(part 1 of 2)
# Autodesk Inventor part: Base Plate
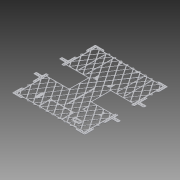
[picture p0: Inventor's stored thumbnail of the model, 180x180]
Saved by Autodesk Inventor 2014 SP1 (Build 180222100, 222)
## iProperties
Created: 2014-06
Part Number: Base Plate
Material: Aluminum 6061
Document SubType Name: Sheet Metal
Designer: Michael
Density: 2.71 g/cm^3
Sheet Metal Rule: Default
Appearance: Aluminum - Flat
Mass: 1196.55 g
Surface Area: 3779.14 cm^2
Volume: 441.53 cm^3
Author: Michael
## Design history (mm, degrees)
node "Face1"
  sketch "Sketch1"
    geometry: L1 (-304.8, -349.25)-(304.8, -349.25); L2 (304.8, -349.25)-(304.8, 349.25); L3 (304.8, 349.25)-(-304.8, 349.25); L4 (-304.8, 349.25)-(-304.8, -349.25); L5 (-304.8, -349.25)-(304.8, 349.25); L6 (304.8, -349.25)-(-304.8, 349.25); 1 further point
    constraints: 12 end point, 2 midpoint, 2 parallel, 1 horizontal, 1 perpendicular
    dimensions: "d0" = 698.5 distance between parallel lines of L1 L3; "d1" = 609.6 distance between parallel lines of L2 L4
sketch "Sketch2"
  geometry: L1 (-304.8, 349.25)-(304.8, 349.25) reference; L2 (-304.8, -349.25)-(-304.8, 349.25) reference; C1 r 2.489 at (-292.1, 336.55); 1 further point
  constraints: 1 centre point
  dimensions: "d3" = 4.9784 diameter of C1; "d4" = 12.7 distance from line of L1 C1.centre; "d5" = 12.7 distance from line of L2 C1.centre
cut "Cut1" sketch "Sketch2" dims "d6" = 3.175 (= Thickness), "d7" = 0
mirror "Mirror1"
sketch "Sketch3"
  geometry: L1 (-304.8, 349.25)-(304.8, 349.25) reference; C1 r 2.489 at (-12.7, 336.55) reference; C2 r 2.489 at (0, 336.55); 2 further points
  constraints: 1 centre point, 1 horizontal alignment, 1 midpoint, 1 vertical alignment
  dimensions: "d11" = 4.9784 diameter of C2
cut "Cut2" sketch "Sketch3" dims "d12" = 3.175 (= Thickness), "d13" = 0
mirror "Mirror2"
mirror "Mirror3"
sketch "Sketch4"
  geometry: L1 (-304.8, -349.25)-(-304.8, 349.25) reference; C1 r 2.489 at (-292.1, 6.35) reference; C2 r 2.489 at (-292.1, 0); 2 further points
  constraints: 1 centre point, 1 horizontal alignment, 1 midpoint, 1 vertical alignment
  dimensions: "d17" = 4.9784 diameter of C2
cut "Cut3" sketch "Sketch4" dims "d18" = 3.175 (= Thickness), "d19" = 0
mirror "Mirror4"
feature "Corner Round1" dims "d20" = 6.35
sketch "Sketch5" dims "d35" = 25.4, "d37" = 12.7 (= d29)
  geometry: L1 (-304.8, -342.9)-(-304.8, 342.9) reference; L2 (298.45, -349.25)-(-298.45, -349.25) reference; L3 (304.8, 342.9)-(304.8, -342.9) reference; L4 (-298.45, 349.25)-(298.45, 349.25) reference; L5 (-222.25, 346.075)-(-222.25, 336.55); L6 (-219.075, 333.375)-(-200.025, 333.375); L7 (-225.425, 349.25)-(-298.45, 349.25); L8 (-196.85, 349.25)-(298.45, 349.25); L9 (-184.15, 333.375)-(-180.975, 333.375); L10 (-180.975, 333.375)-(-161.925, 333.375); L11 (-142.875, 333.375)-(-123.825, 333.375); L12 (-104.775, 333.375)-(-85.725, 333.375); L13 (-66.675, 333.375)-(-47.625, 333.375); L14 (-28.575, 333.375)-(-9.525, 333.375); L15 (0, 336.55)-(0, 349.25); L16 (-196.85, 349.25)-(-225.425, 349.25); L17 (-225.425, 349.25)-(0, 349.25); L18 (-222.25, 346.075)-(-222.25, 336.55); L19 (-219.075, 333.375)-(-200.025, 333.375); C1 r 2.489 at (292.1, 0) reference; C2 r 2.489 at (-292.1, 0) reference; C3 r 2.489 at (292.1, -6.35) reference; C4 r 2.489 at (292.1, -19.05) reference; C5 r 2.489 at (292.1, -31.75) reference; C6 r 2.489 at (292.1, -44.45) reference; C7 r 2.489 at (292.1, -57.15) reference; C8 r 2.489 at (292.1, -69.85) reference; C9 r 2.489 at (292.1, -82.55) reference; C10 r 2.489 at (292.1, -95.25) reference; C11 r 2.489 at (292.1, -107.95) reference; C12 r 2.489 at (292.1, -120.65) reference; C13 r 2.489 at (292.1, -133.35) reference; C14 r 2.489 at (292.1, -146.05) reference; C15 r 2.489 at (292.1, -158.75) reference; C16 r 2.489 at (292.1, -171.45) reference; C17 r 2.489 at (292.1, -184.15) reference; C18 r 2.489 at (292.1, -196.85) reference; C19 r 2.489 at (292.1, -209.55) reference; C20 r 2.489 at (292.1, -222.25) reference; C21 r 2.489 at (292.1, -234.95) reference; C22 r 2.489 at (292.1, -247.65) reference; C23 r 2.489 at (292.1, -260.35) reference; C24 r 2.489 at (292.1, -273.05) reference; C25 r 2.489 at (292.1, -285.75) reference; C26 r 2.489 at (292.1, -298.45) reference; C27 r 2.489 at (292.1, -311.15) reference; C28 r 2.489 at (292.1, -323.85) reference; C29 r 2.489 at (-292.1, -6.35) reference; C30 r 2.489 at (-292.1, -19.05) reference; C31 r 2.489 at (-292.1, -31.75) reference; C32 r 2.489 at (-292.1, -44.45) reference; C33 r 2.489 at (-292.1, -57.15) reference; C34 r 2.489 at (-292.1, -69.85) reference; C35 r 2.489 at (-292.1, -82.55) reference; C36 r 2.489 at (-292.1, -95.25) reference; C37 r 2.489 at (-292.1, -107.95) reference; C38 r 2.489 at (-292.1, -120.65) reference; C39 r 2.489 at (-292.1, -133.35) reference; C40 r 2.489 at (-292.1, -146.05) reference; C41 r 2.489 at (-292.1, -158.75) reference; C42 r 2.489 at (-292.1, -171.45) reference; C43 r 2.489 at (-292.1, -184.15) reference; C44 r 2.489 at (-292.1, -196.85) reference; C45 r 2.489 at (-292.1, -209.55) reference; C46 r 2.489 at (-292.1, -222.25) reference; C47 r 2.489 at (-292.1, -234.95) reference; C48 r 2.489 at (-292.1, -247.65) reference; C49 r 2.489 at (-292.1, -260.35) reference; C50 r 2.489 at (-292.1, -273.05) reference; C51 r 2.489 at (-292.1, -285.75) reference; C52 r 2.489 at (-292.1, -298.45) reference; C53 r 2.489 at (-292.1, -311.15) reference; C54 r 2.489 at (-292.1, -323.85) reference; C55 r 2.489 at (0, -336.55) reference; C56 r 2.489 at (12.7, -336.55) reference; C57 r 2.489 at (25.4, -336.55) reference; C58 r 2.489 at (38.1, -336.55) reference; C59 r 2.489 at (50.8, -336.55) reference; C60 r 2.489 at (63.5, -336.55) reference; C61 r 2.489 at (76.2, -336.55) reference; C62 r 2.489 at (88.9, -336.55) reference; C63 r 2.489 at (101.6, -336.55) reference; C64 r 2.489 at (114.3, -336.55) reference; A1 r 6.35 centre (-298.45, 342.9) between (-298.45, 349.25) and (-304.8, 342.9) reference; A2 r 6.35 centre (-298.45, -342.9) between (-304.8, -342.9) and (-298.45, -349.25) reference; A3 r 6.35 centre (298.45, -342.9) between (298.45, -349.25) and (304.8, -342.9) reference; A4 r 6.35 centre (298.45, 342.9) between (304.8, 342.9) and (298.45, 349.25) reference; A5 r 3.175 centre (-225.425, 346.075) between (-222.25, 346.075) and (-225.425, 349.25); A6 r 3.175 centre (-219.075, 336.55) between (-222.25, 336.55) and (-219.075, 333.375); A7 r 3.175 centre (-200.025, 336.55) between (-200.025, 333.375) and (-196.85, 336.55); A8 r 3.175 centre (-180.975, 336.55) between (-184.15, 336.55) and (-180.975, 333.375); A9 r 3.175 centre (-161.925, 336.55) between (-161.925, 333.375) and (-158.75, 336.55); A10 r 3.175 centre (-142.875, 336.55) between (-146.05, 336.55) and (-142.875, 333.375); A11 r 3.175 centre (-123.825, 336.55) between (-123.825, 333.375) and (-120.65, 336.55); A12 r 3.175 centre (-104.775, 336.55) between (-107.95, 336.55) and (-104.775, 333.375); A13 r 3.175 centre (-85.725, 336.55) between (-85.725, 333.375) and (-82.55, 336.55); A14 r 3.175 centre (-66.675, 336.55) between (-69.85, 336.55) and (-66.675, 333.375); A15 r 3.175 centre (-47.625, 336.55) between (-47.625, 333.375) and (-44.45, 336.55); A16 r 3.175 centre (-28.575, 336.55) between (-31.75, 336.55) and (-28.575, 333.375); A17 r 3.175 centre (-9.525, 336.55) between (-9.525, 333.375) and (-6.35, 336.55); A18 r 3.175 centre (-225.425, 346.075) between (-222.25, 346.075) and (-225.425, 349.25); A19 r 3.175 centre (-219.075, 336.55) between (-222.25, 336.55) and (-219.075, 333.375)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; 2 further points
  constraints: 30 end point, 30 point on circle, 23 tangent, 20 centre point, 6 collinear, 5 point on line, 4 perpendicular, 2 coincident, 2 equal radius, 2 horizontal alignment, 1 horizontal, 51 other
  dimensions: "d21" = 6.35 distance from line of C195.centre L5; "d23" = 15.875 distance between parallel lines of L4 L6; "d26" = 3.175 radius of A5; "d27" = 3.175 radius of A8; "d28" = 3.175 horizontal distance of A8.centre L9.start; "d29" = 12.7 diameter of C201; "d32" = 38.1 distance of L6.start L10.start; "d38" = 3.175 radius of A17
sketch "Sketch6" dims "d64" = 25.4
  geometry: L1 (298.45, -349.25)-(-298.45, -349.25) reference; L2 (-298.45, 349.25)-(298.45, 349.25) reference; L3 (277.812, -328.612)-(-277.813, -328.613); L4 (-277.813, -328.613)-(-277.812, 328.612); L5 (-277.812, 328.612)-(277.812, 328.613); L6 (277.812, 328.613)-(277.812, -328.612); L7 (277.812, -328.612)-(-277.812, 328.612); L8 (-277.813, -328.613)-(277.812, 328.613); L9 (271.463, -322.263)-(-271.463, -322.263); L10 (-271.463, -322.263)-(-271.463, 322.263); L11 (-271.463, 322.263)-(271.463, 322.263); L12 (271.463, 322.263)-(271.463, -322.263); L13 (271.463, -322.263)-(-271.463, 322.263); L14 (-271.463, -322.263)-(271.463, 322.263); L15 (-222.477, 306.978)-(-182.472, 266.972); L16 (-182.472, 266.972)-(-222.477, 226.967); L17 (-222.477, 226.967)-(-262.482, 266.972); L18 (-262.482, 266.972)-(-222.477, 306.978); L19 (-177.982, 262.482)-(-137.976, 222.477); L20 (-137.976, 222.477)-(-177.982, 182.472); L21 (-177.982, 182.472)-(-217.987, 222.477); L22 (-217.987, 222.477)-(-177.982, 262.482); L23 (-133.486, 226.967)-(-173.491, 266.972); L24 (-173.491, 266.972)-(-133.486, 306.978); L25 (-133.486, 306.978)-(-93.481, 266.972); L26 (-93.481, 266.972)-(-133.486, 226.967); L27 (-88.991, 262.482)-(-48.986, 222.477); L28 (-48.986, 222.477)-(-88.991, 182.472); L29 (-88.991, 182.472)-(-128.996, 222.477); L30 (-128.996, 222.477)-(-88.991, 262.482); L31 (-44.495, 306.978)-(-4.49, 266.972); L32 (-4.49, 266.972)-(-44.495, 226.967); L33 (-44.495, 226.967)-(-84.501, 266.972); L34 (-84.501, 266.972)-(-44.495, 306.978); L35 (0, 349.25)-(0, -349.25); L36 (0, 266.972)-(-4.49, 266.972); L37 (-262.482, 266.972)-(-271.462, 266.972); L38 (-182.472, 266.972)-(-173.491, 266.972); L39 (-4.49, 266.972)-(4.49, 266.972); L40 (-182.472, 177.982)-(-222.477, 137.976); L41 (-222.477, 137.976)-(-262.482, 177.982); L42 (-262.482, 177.982)-(-222.477, 217.987); L43 (-222.477, 217.987)-(-182.472, 177.982); L44 (-182.472, 88.991)-(-222.477, 48.986); L45 (-222.477, 48.986)-(-262.482, 88.991); L46 (-262.482, 88.991)-(-222.477, 128.996); L47 (-222.477, 128.996)-(-182.472, 88.991); L48 (-182.472, 0)-(-222.477, -40.005); L49 (-222.477, -40.005)-(-262.482, 0); L50 (-262.482, 0)-(-222.477, 40.005); L51 (-222.477, 40.005)-(-182.472, 0); L52 (-182.472, -88.991)-(-222.477, -128.996); L53 (-222.477, -128.996)-(-262.482, -88.991); L54 (-262.482, -88.991)-(-222.477, -48.986); L55 (-222.477, -48.986)-(-182.472, -88.991); L56 (-182.472, -177.982)-(-222.477, -217.987); L57 (-222.477, -217.987)-(-262.482, -177.982); L58 (-262.482, -177.982)-(-222.477, -137.976); L59 (-222.477, -137.976)-(-182.472, -177.982); L60 (-182.472, -266.972)-(-222.477, -306.978); L61 (-222.477, -306.978)-(-262.482, -266.972); L62 (-262.482, -266.972)-(-222.477, -226.967); L63 (-222.477, -226.967)-(-182.472, -266.972); L64 (-222.477, -306.978)-(-222.477, -322.263)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; 14 further points
  constraints: 126 end point, 10 midpoint, 7 equal length, 7 parallel, 4 collinear, 4 perpendicular, 4 point on line, 3 horizontal alignment, 2 horizontal, 1 vertical, 99 other
  dimensions: "d39" = 555.625 distance between parallel lines of L6 L4; "d40" = 657.225 distance between parallel lines of L5 L3; "d41" = 6.35 distance between parallel lines of L4 L10; "d42" = 6.35 distance between parallel lines of L5 L11; "d43" = 45 deg angle of L11 L18; "d44" = 6.35 distance between parallel lines of L16 L22; "d46" = 6.35 distance between parallel lines of L19 L23 (= d44); "d47" = 6.35 distance between parallel lines of L26 L30 (= d44); "d48" = 6.35 distance between parallel lines of L27 L33 (= d44); "d61" = 88.99079 distance of L15.end L40.start
cut "Cut4" sketch "Sketch6" dims "d50" = 3.175 (= Thickness), "d51" = 0
feature "Corner Round2" dims "d52" = 3.175
pattern_linear "Rectangular Pattern3" dims "d55" = 88.99079
pattern_linear "Rectangular Pattern4" dims "d58" = 88.99079
sketch "Sketch7"
  geometry: L1 (-260.237, 180.227)-(-224.722, 215.742) reference; L2 (-220.232, 304.733)-(-184.717, 269.217) reference; L3 (-224.722, 229.212)-(-260.237, 264.727) reference; L4 (-217.987, 222.477)-(-177.982, 262.482); L5 (-177.982, 262.482)-(-137.976, 222.477); L6 (-137.976, 222.477)-(-177.982, 182.472); L7 (-177.982, 182.472)-(-217.987, 222.477); 2 further points
  constraints: 8 end point, 3 collinear, 9 other
cut "Cut5" sketch "Sketch7" dims "d66" = 3.175 (derived), "d67" = 0
feature "Corner Round3" dims "d68" = 3.175
sketch "Sketch8"
  geometry: L1 (-260.237, 269.217)-(-224.722, 304.733) reference; L2 (-224.722, 229.212)-(-260.237, 264.727) reference; L3 (-298.45, 349.25)-(298.45, 349.25) reference; L4 (-262.482, 306.978)-(-262.482, 275.953); L5 (-262.482, 275.953)-(-231.457, 306.978); L6 (-231.457, 306.978)-(-262.482, 306.978); L7 (-224.722, 304.733)-(-222.477, 306.978); L8 (-220.232, 304.733)-(-222.477, 306.978); L9 (-260.237, 269.217)-(-262.482, 266.972); L10 (-260.237, 264.727)-(-262.482, 266.972); A1 r 3.175 centre (-222.477, 302.488) between (-220.232, 304.733) and (-224.722, 304.733) reference; A2 r 3.175 centre (-257.992, 266.972) between (-260.237, 269.217) and (-260.237, 264.727) reference; 1 further point
  constraints: 14 end point, 6 perpendicular, 4 tangent, 1 horizontal alignment, 1 parallel, 1 vertical alignment
  dimensions: "d75" = 6.35 distance between parallel lines of L1 L5
cut "Cut6" sketch "Sketch8" dims "d76" = 3.175 (derived), "d77" = 0
feature "Corner Round4" dims "d78" = 3.175
mirror "Mirror5"
mirror "Mirror6"
sketch "Sketch9"
  geometry: L1 (-171.246, 269.217)-(-135.731, 304.733) reference; L2 (-220.232, 304.733)-(-184.717, 269.217) reference; L3 (-298.45, 349.25)-(298.45, 349.25) reference; L4 (-213.497, 306.978)-(-177.982, 271.463); L5 (-177.982, 271.463)-(-142.466, 306.978); L6 (-142.466, 306.978)-(-213.497, 306.978); 2 further points
  constraints: 6 end point, 3 parallel, 1 horizontal alignment
  dimensions: "d79" = 6.35 distance between parallel lines of L2 L4; "d80" = 6.35 distance between parallel lines of L1 L5
cut "Cut7" sketch "Sketch9" dims "d81" = 3.175 (derived), "d82" = 0
feature "Corner Round5" dims "d83" = 3.175
pattern_linear "Rectangular Pattern6" dims "d86" = 88.99079
mirror "Mirror7"
sketch "Sketch11"
  geometry: L1 (-260.237, 180.227)-(-224.722, 215.742) reference; L2 (-224.722, 229.212)-(-260.237, 264.727) reference; L3 (-262.482, 257.992)-(-262.482, 186.962); L4 (-262.482, 186.962)-(-226.967, 222.477); L5 (-226.967, 222.477)-(-262.482, 257.992); 2 further points
  constraints: 6 end point, 2 parallel, 1 perpendicular, 1 vertical, 1 vertical alignment
  dimensions: "d91" = 6.35 distance between parallel lines of L2 L5; "d92" = 6.35 distance between parallel lines of L1 L4 (derived)
cut "Cut9" sketch "Sketch11" dims "d93" = 3.175 (derived), "d94" = 0
feature "Corner Round6" dims "d95" = 3.175
pattern_linear "Rectangular Pattern7" dims "d98" = 88.99079
mirror "Mirror8"
sketch "Sketch12" dims "d106" = 25.4, "d113" = 25.4
  geometry: L1 (-304.8, -342.9)-(-304.8, 342.9) reference; L2 (298.45, -349.25)-(-298.45, -349.25) reference; L3 (285.75, 330.2)-(-285.75, 330.2); L4 (-285.75, 330.2)-(-285.75, -330.2); L5 (-285.75, -330.2)-(285.75, -330.2); L6 (285.75, -330.2)-(285.75, 330.2); L7 (285.75, 330.2)-(-285.75, -330.2); L8 (-285.75, 330.2)-(285.75, -330.2); L9 (-255.746, -329.309)-(-280.325, -293.092); L10 (-280.325, -293.092)-(-255.746, -256.876); L11 (-255.746, -256.876)-(-231.167, -293.092); L12 (-231.167, -293.092)-(-255.746, -329.309); L13 (-280.325, -293.092)-(-285.75, -293.092); L14 (-255.746, -329.309)-(-255.746, -330.2); L15 (-223.493, -293.092)-(-198.914, -256.876); L16 (-198.914, -329.309)-(-223.493, -293.092); L17 (-198.914, -256.876)-(-174.335, -293.092); L18 (-174.335, -293.092)-(-198.914, -329.309); L19 (-166.66, -293.092)-(-142.081, -256.876); L20 (-142.081, -329.309)-(-166.66, -293.092); L21 (-142.081, -256.876)-(-117.502, -293.092); L22 (-117.502, -293.092)-(-142.081, -329.309); L23 (-109.828, -293.092)-(-85.249, -256.876); L24 (-85.249, -329.309)-(-109.828, -293.092); L25 (-85.249, -256.876)-(-60.67, -293.092); L26 (-60.67, -293.092)-(-85.249, -329.309); L27 (-52.995, -293.092)-(-28.416, -256.876); L28 (-28.416, -329.309)-(-52.995, -293.092); L29 (-28.416, -256.876)-(-3.837, -293.092); L30 (-3.837, -293.092)-(-28.416, -329.309); L31 (3.837, -293.092)-(28.416, -256.876); L32 (28.416, -329.309)-(3.837, -293.092); L33 (28.416, -256.876)-(52.995, -293.092); L34 (52.995, -293.092)-(28.416, -329.309); L35 (60.67, -293.092)-(85.249, -256.876); L36 (85.249, -329.309)-(60.67, -293.092); L37 (85.249, -256.876)-(109.828, -293.092); L38 (109.828, -293.092)-(85.249, -329.309); L39 (117.502, -293.092)-(142.081, -256.876); L40 (142.081, -329.309)-(117.502, -293.092); L41 (142.081, -256.876)-(166.66, -293.092); L42 (166.66, -293.092)-(142.081, -329.309); L43 (174.335, -293.092)-(198.914, -256.876); L44 (198.914, -329.309)-(174.335, -293.092); L45 (198.914, -256.876)-(223.493, -293.092); L46 (223.493, -293.092)-(198.914, -329.309); L47 (231.167, -293.092)-(255.746, -256.876); L48 (255.746, -329.309)-(231.167, -293.092); L49 (255.746, -256.876)-(280.325, -293.092); L50 (280.325, -293.092)-(255.746, -329.309); L51 (-255.746, -173.135)-(-231.167, -209.352); L52 (-255.746, -245.568)-(-280.325, -209.352); L53 (-231.167, -209.352)-(-255.746, -245.568); L54 (-280.325, -209.352)-(-255.746, -173.135); L55 (-198.914, -245.568)-(-223.493, -209.352); L56 (-174.335, -209.352)-(-198.914, -245.568); L57 (-223.493, -209.352)-(-198.914, -173.135); L58 (-198.914, -173.135)-(-174.335, -209.352); L59 (-166.66, -209.352)-(-142.081, -173.135); L60 (-142.081, -245.568)-(-166.66, -209.352); L61 (-117.502, -209.352)-(-142.081, -245.568); L62 (-109.828, -209.352)-(-85.249, -173.135); L63 (-85.249, -245.568)-(-109.828, -209.352); L64 (-60.67, -209.352)-(-85.249, -245.568)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; 1 further point
  constraints: 660 end point, 5 perpendicular, 4 parallel, 4 point on line, 3 equal length, 2 horizontal, 2 midpoint, 1 horizontal alignment, 1 vertical, 1 vertical alignment, 632 other
  dimensions: "d99" = 19.05 distance between parallel lines of L1 L4; "d100" = 19.05 distance between parallel lines of L2 L5; "d103" = 56.8325 distance of L9.end L15.start; "d110" = 83.74063 distance of L11.end L51.end; "d116" = 6.35 distance between parallel lines of L16 L11; "d117" = 6.35 distance between parallel lines of L52 L11
cut "Cut10" sketch "Sketch12" dims "d118" = 3.175 (derived), "d119" = 0
feature "Corner Round7" dims "d120" = 3.175
pattern_linear "Rectangular Pattern8" dims "d123" = 56.8325
pattern_linear "Rectangular Pattern9" dims "d126" = 83.74063
sketch "Sketch13"
  geometry: L1 (-201.541, -241.697)-(-222.283, -211.135) reference; L2 (-232.377, -211.135)-(-253.119, -241.697) reference; L3 (-222.283, -291.309)-(-201.541, -260.747) reference; L4 (-253.119, -260.747)-(-232.377, -291.309) reference; L5 (-227.33, -215.005)-(-251.909, -251.222); L6 (-251.909, -251.222)-(-227.33, -287.438); L7 (-227.33, -287.438)-(-202.751, -251.222); L8 (-202.751, -251.222)-(-227.33, -215.005); 1 further point
  constraints: 8 end point, 5 parallel
  dimensions: "d127" = 6.35 distance between parallel lines of L2 L5; "d128" = 6.35 distance between parallel lines of L1 L8 (derived); "d129" = 6.35 distance between parallel lines of L3 L7 (derived); "d130" = 6.35 distance between parallel lines of L4 L6 (derived)
cut "Cut11" sketch "Sketch13" dims "d131" = 3.175 (derived), "d132" = 0
feature "Corner Round8" dims "d133" = 3.175
pattern_linear "Rectangular Pattern10" dims "d136" = 56.8325
pattern_linear "Rectangular Pattern11" dims "d139" = 83.74063
sketch "Sketch14"
  geometry: L1 (-279.115, 294.875)-(-258.373, 325.438) reference; L2 (-253.119, 325.438)-(-232.377, 294.875) reference; L3 (-279.115, -291.309)-(-258.373, -260.747) reference; L4 (-253.119, -260.747)-(-232.377, -291.309) reference; L5 (-298.45, 349.25)-(298.45, 349.25) reference; L6 (-280.325, 329.309)-(-280.325, 304.4); L7 (-280.325, 304.4)-(-263.421, 329.309); L8 (-263.421, 329.309)-(-280.325, 329.309); L9 (-258.373, 325.438)-(-255.746, 329.309); L10 (-253.119, 325.438)-(-255.746, 329.309); L11 (-279.115, 294.875)-(-280.325, 293.092); L12 (-279.115, 291.309)-(-280.325, 293.092); A1 r 3.175 centre (-276.488, 293.092) between (-279.115, 294.875) and (-279.115, 291.309) reference; A2 r 3.175 centre (-255.746, 323.655) between (-253.119, 325.438) and (-258.373, 325.438) reference; 1 further point
  constraints: 14 end point, 4 parallel, 4 tangent, 2 collinear, 2 perpendicular, 1 horizontal alignment, 1 vertical alignment
  dimensions: "d140" = 6.35 distance between parallel lines of L1 L7
cut "Cut12" sketch "Sketch14" dims "d141" = 3.175 (derived), "d142" = 0
feature "Corner Round9" dims "d143" = 1.5875
feature "Corner Round10" dims "d144" = 3.175
mirror "Mirror9"
mirror "Mirror10"
sketch "Sketch15"
  geometry: L1 (-277.15, 329.309)-(-266.417, 329.309) reference; L2 (-222.283, 294.875)-(-201.541, 325.438) reference; L3 (-253.119, 325.438)-(-232.377, 294.875) reference; L4 (-298.45, 349.25)-(298.45, 349.25) reference; L5 (-248.072, 329.309)-(-227.33, 298.746); L6 (-227.33, 298.746)-(-206.588, 329.309); L7 (-248.072, 329.309)-(-206.588, 329.309); 2 further points
  constraints: 6 end point, 3 parallel, 2 horizontal alignment, 1 midpoint
  dimensions: "d146" = 6.35 distance between parallel lines of L3 L5; "d147" = 6.35 distance between parallel lines of L2 L6 (derived)
cut "Cut13" sketch "Sketch15" dims "d148" = 3.175 (derived), "d149" = 0
feature "Corner Round11" dims "d150" = 3.175
pattern_linear "Rectangular Pattern12" dims "d153" = 56.8325
sketch "Sketch16"
  geometry: L1 (-258.373, 260.747)-(-279.115, 291.309) reference; L2 (-279.115, 211.135)-(-258.373, 241.697) reference; L3 (-298.45, 349.25)-(298.45, 349.25) reference; L4 (-280.325, 281.784)-(-280.325, 220.659); L5 (-280.325, 220.659)-(-259.583, 251.222); L6 (-259.583, 251.222)-(-280.325, 281.784); 2 further points
  constraints: 6 end point, 2 parallel, 1 perpendicular, 1 vertical alignment
  dimensions: "d154" = 6.35 distance between parallel lines of L1 L6; "d155" = 6.35 distance between parallel lines of L2 L5
cut "Cut14" sketch "Sketch16" dims "d156" = 3.175 (derived), "d157" = 0
feature "Corner Round13" dims "d159" = 3.175
feature "Corner Round14" dims "d160" = 1.5875
pattern_linear "Rectangular Pattern13" dims "d163" = 83.74063
mirror "Mirror11"
mirror "Mirror12"
sketch "Sketch17"
  geometry: L1 (-298.45, 349.25)-(298.45, 349.25) reference; L2 (-222.987, 342.163)-(-230.075, 349.25); L3 (-214.312, 330.2)-(-192.087, 330.2); L4 (-185.737, 336.55)-(-185.737, 336.55); L5 (-177.8, 344.487)-(-177.8, 349.25); C1 r 2.489 at (-177.8, 336.55) reference; C2 r 2.489 at (-190.5, 336.55) reference; C3 r 2.489 at (-203.2, 336.55) reference; C4 r 2.489 at (-215.9, 336.55) reference; C5 r 2.489 at (-228.6, 336.55) reference; A1 r 7.938 centre (-228.6, 336.55) between (-222.987, 342.163) and (-220.662, 336.55); A2 r 6.35 centre (-214.312, 336.55) between (-220.662, 336.55) and (-214.312, 330.2); A3 r 7.938 centre (-177.8, 336.55) between (-185.737, 336.55) and (-177.8, 344.487); A4 r 6.35 centre (-192.087, 336.55) between (-192.087, 330.2) and (-185.737, 336.55); 1 further point
  constraints: 8 end point, 8 point on circle, 6 tangent, 4 centre point, 2 coincident, 2 perpendicular, 2 point on line, 1 horizontal, 1 horizontal alignment
  dimensions: "d164" = 15.875 diameter of A1; "d165" = 45 deg angle of L1 L2; "d166" = 6.35 radius of A2; "d167" = 15.875 diameter of A3 (derived); "d168" = 6.35 radius of A4
cut "Cut15" sketch "Sketch17" dims "d169" = 3.175 (derived), "d170" = 0
sketch "Sketch18"
  geometry: L1 (-177.8, 349.25)-(298.45, 349.25) reference; L2 (-177.8, 349.25)-(-177.8, 344.487) reference; L3 (-163.512, 330.2)-(-141.287, 330.2); L4 (-127, 344.487)-(-127, 349.25); C1 r 2.489 at (-177.8, 336.55) reference; C2 r 2.489 at (-165.1, 336.55) reference; C3 r 2.489 at (-152.4, 336.55) reference; C4 r 2.489 at (-139.7, 336.55) reference; C5 r 2.489 at (-127, 336.55) reference; A1 r 6.35 centre (-163.512, 336.55) between (-169.862, 336.55) and (-163.512, 330.2); A2 r 6.35 centre (-141.287, 336.55) between (-141.287, 330.2) and (-134.938, 336.55); A3 r 7.938 centre (-177.8, 336.55) between (-169.862, 336.55) and (-177.8, 344.487); A4 r 7.938 centre (-127, 336.55) between (-127, 344.487) and (-134.938, 336.55); 10 further points; 2 other entities
  constraints: 8 point on circle, 4 centre point, 4 end point, 4 tangent, 3 coincident, 3 point on line, 1 horizontal, 1 horizontal alignment, 1 perpendicular, 1 vertical alignment, 6 other
  dimensions: "d175" = 6.35 radius of A1; "d176" = 6.35 radius of A2 (derived); "d177" = 7.9375 radius of A4
cut "Cut16" sketch "Sketch18" dims "d178" = 3.175 (derived), "d179" = 0
pattern_linear "Rectangular Pattern14" dims "d182" = 50.8
mirror "Mirror13"
sketch "Sketch19"
  geometry: L1 (25.4, 344.487)-(25.4, 349.25) reference; L2 (-25.4, 349.25)-(25.4, 349.25) reference; L3 (-25.4, 349.25)-(-25.4, 344.487) reference; L4 (242.08, -329.309)-(212.58, -329.309) reference; L5 (-11.112, 330.2)-(0, 330.2); L6 (0, 330.2)-(0, 349.25); L7 (11.112, 330.2)-(0, 330.2); C1 r 2.489 at (-25.4, 336.55) reference; C2 r 2.489 at (-12.7, 336.55) reference; C3 r 2.489 at (12.7, 336.55) reference; C4 r 2.489 at (0, 336.55) reference; A1 r 7.938 centre (-25.4, 336.55) between (-25.4, 344.487) and (-33.337, 336.55) reference; A2 r 7.938 centre (-25.4, 336.55) between (-17.462, 336.55) and (-25.4, 344.487); A3 r 6.35 centre (-11.112, 336.55) between (-17.462, 336.55) and (-11.112, 330.2); A4 r 6.35 centre (11.112, 336.55) between (11.112, 330.2) and (17.462, 336.55); A5 r 7.938 centre (25.4, 336.55) between (25.4, 344.487) and (17.462, 336.55); 1 further point
  constraints: 8 point on circle, 6 end point, 4 centre point, 4 symmetric about line, 2 tangent, 1 coincident, 1 horizontal alignment, 1 midpoint, 1 parallel, 2 other
  dimensions: "d183" = 6.35 radius of A3
cut "Cut17" sketch "Sketch19" dims "d184" = 3.175 (derived), "d185" = 0
sketch "Sketch20"
  geometry: L1 (-39.687, 330.2)-(-61.912, 330.2) reference; L2 (-90.487, 330.2)-(-112.712, 330.2) reference; L3 (-141.287, 330.2)-(-163.512, 330.2) reference; L4 (-192.087, 330.2)-(-214.312, 330.2) reference; L5 (-222.987, 342.163)-(-230.075, 349.25) reference; L6 (-298.45, 349.25)-(-230.075, 349.25) reference; L7 (-304.8, -342.9)-(-304.8, 342.9) reference; L8 (298.45, -349.25)-(-298.45, -349.25) reference; L9 (304.8, 342.9)-(304.8, -342.9) reference; L10 (230.075, 349.25)-(298.45, 349.25) reference; L11 (230.075, 349.25)-(222.987, 342.163) reference; L12 (214.312, 330.2)-(192.087, 330.2) reference; L13 (163.512, 330.2)-(141.287, 330.2) reference; L14 (112.712, 330.2)-(90.487, 330.2) reference; L15 (61.912, 330.2)-(39.687, 330.2) reference; L16 (11.112, 330.2)-(-11.112, 330.2) reference; L17 (-226.355, 345.53)-(-222.987, 342.163); L18 (-235.335, 349.25)-(-298.45, 349.25); A1 r 7.938 centre (-25.4, 336.55) between (-17.462, 336.55) and (-33.337, 336.55) reference; A2 r 6.35 centre (-39.687, 336.55) between (-39.687, 330.2) and (-33.337, 336.55) reference; A3 r 6.35 centre (-61.912, 336.55) between (-68.262, 336.55) and (-61.912, 330.2) reference; A4 r 7.938 centre (-76.2, 336.55) between (-68.262, 336.55) and (-84.137, 336.55) reference; A5 r 6.35 centre (-90.487, 336.55) between (-90.487, 330.2) and (-84.137, 336.55) reference; A6 r 6.35 centre (-112.712, 336.55) between (-119.062, 336.55) and (-112.712, 330.2) reference; A7 r 7.938 centre (-127, 336.55) between (-119.062, 336.55) and (-134.938, 336.55) reference; A8 r 6.35 centre (-141.287, 336.55) between (-141.287, 330.2) and (-134.938, 336.55) reference; A9 r 6.35 centre (-163.512, 336.55) between (-169.862, 336.55) and (-163.512, 330.2) reference; A10 r 7.937 centre (-177.8, 336.55) between (-169.862, 336.55) and (-185.737, 336.55) reference; A11 r 6.35 centre (-192.087, 336.55) between (-192.087, 330.2) and (-185.737, 336.55) reference; A12 r 6.35 centre (-214.312, 336.55) between (-220.662, 336.55) and (-214.312, 330.2) reference; A13 r 7.937 centre (-228.6, 336.55) between (-220.662, 336.55) and (-222.987, 342.163) reference; A14 r 6.35 centre (-298.45, 342.9) between (-298.45, 349.25) and (-304.8, 342.9) reference; A15 r 6.35 centre (-298.45, -342.9) between (-304.8, -342.9) and (-298.45, -349.25) reference; A16 r 6.35 centre (298.45, -342.9) between (298.45, -349.25) and (304.8, -342.9) reference; A17 r 6.35 centre (298.45, 342.9) between (304.8, 342.9) and (298.45, 349.25) reference; A18 r 7.937 centre (228.6, 336.55) between (222.987, 342.163) and (220.662, 336.55) reference; A19 r 6.35 centre (214.312, 336.55) between (214.312, 330.2) and (220.662, 336.55) reference; A20 r 6.35 centre (192.087, 336.55) between (185.737, 336.55) and (192.087, 330.2) reference; A21 r 7.937 centre (177.8, 336.55) between (185.737, 336.55) and (169.862, 336.55) reference; A22 r 6.35 centre (163.512, 336.55) between (163.512, 330.2) and (169.862, 336.55) reference; A23 r 6.35 centre (141.287, 336.55) between (134.938, 336.55) and (141.287, 330.2) reference; A24 r 7.938 centre (127, 336.55) between (134.938, 336.55) and (119.062, 336.55) reference; A25 r 6.35 centre (112.712, 336.55) between (112.712, 330.2) and (119.062, 336.55) reference; A26 r 6.35 centre (90.487, 336.55) between (84.137, 336.55) and (90.487, 330.2) reference; A27 r 7.938 centre (76.2, 336.55) between (84.137, 336.55) and (68.262, 336.55) reference; A28 r 6.35 centre (61.912, 336.55) between (61.912, 330.2) and (68.262, 336.55) reference; A29 r 6.35 centre (39.687, 336.55) between (33.337, 336.55) and (39.687, 330.2) reference; A30 r 7.938 centre (25.4, 336.55) between (33.337, 336.55) and (17.462, 336.55) reference; A31 r 6.35 centre (11.112, 336.55) between (11.112, 330.2) and (17.462, 336.55) reference; A32 r 6.35 centre (-11.112, 336.55) between (-17.462, 336.55) and (-11.112, 330.2) reference; A33 r 12.7 centre (-235.335, 336.55) between (-226.355, 345.53) and (-235.335, 349.25); 1 further point
  constraints: 4 end point, 4 tangent, 2 point on circle, 2 point on line, 1 centre point, 1 collinear, 1 perpendicular
  dimensions: "d186" = 12.7 radius of A33
cut "Cut18" sketch "Sketch20" dims "d187" = 3.175 (derived), "d188" = 0
mirror "Mirror14"
mirror "Mirror15"
node "Face2"
  sketch "Sketch21"
    geometry: L1 (-298.45, 349.25)-(-235.335, 349.25) reference; L2 (-304.8, -342.9)-(-304.8, 342.9) reference; L3 (-292.1, 349.25)-(-292.1, 107.95); L4 (-311.15, 95.25)-(-349.25, 95.25); L5 (-355.6, 101.6)-(-355.6, 114.3); L6 (-349.25, 120.65)-(-311.15, 120.65); L7 (-304.8, 120.65)-(-304.8, 95.25); L8 (-304.8, 88.9)-(-304.8, 108.108); L9 (-304.8, 127)-(-304.8, 169.069); L10 (-304.8, 88.9)-(-304.8, 127); C1 r 2.489 at (-292.1, 133.35) reference; A1 r 6.35 centre (-311.15, 127) between (-311.15, 120.65) and (-304.8, 127); A2 r 6.35 centre (-311.15, 88.9) between (-304.8, 88.9) and (-311.15, 95.25); A3 r 6.35 centre (-349.25, 101.6) between (-355.6, 101.6) and (-349.25, 95.25); A4 r 6.35 centre (-349.25, 114.3) between (-349.25, 120.65) and (-355.6, 114.3); 4 further points
    constraints: 16 end point, 13 point on line, 10 tangent, 8 point on circle, 4 centre point, 3 equal radius, 2 parallel, 1 collinear, 1 horizontal, 1 horizontal alignment, 1 midpoint, 1 perpendicular, 1 vertical
    dimensions: "d189" = 241.3 distance of L3.start L3.end; "d190" = 50.8 distance of point (-355.6, 120.65) L7.start; "d191" = 25.4 distance between parallel lines of L6 L4; "d210" = 6.35 radius of A1
cut "Cut19" dims "d204" = 3.175 (derived), "d205" = 0
pattern_linear "Rectangular Pattern16" dims "d213" = 12.7
mirror "Mirror17"
mirror "Mirror18"
sketch "Sketch23"
  geometry: L1 (-304.8, -88.9)-(-304.8, 88.9) reference; L2 (-232.377, -43.653)-(-253.119, -74.216) reference; L3 (-258.373, -74.216)-(-279.115, -43.653) reference; L4 (-279.115, -40.087)-(-258.373, -9.525) reference; L5 (-253.119, -9.525)-(-232.377, -40.087) reference; L6 (-232.377, 40.087)-(-253.119, 9.525) reference; L7 (-258.373, 9.525)-(-279.115, 40.087) reference; L8 (-279.115, 43.653)-(-258.373, 74.216) reference; L9 (-253.119, 74.216)-(-232.377, 43.653) reference; L10 (-175.545, -43.653)-(-196.287, -74.216) reference; L11 (-201.541, -74.216)-(-222.283, -43.653) reference; L12 (-222.283, -40.087)-(-201.541, -9.525) reference; L13 (-196.287, -9.525)-(-175.545, -40.087) reference; L14 (-118.712, -43.653)-(-139.454, -74.216) reference; L15 (-144.708, -74.216)-(-165.45, -43.653) reference; L16 (-165.45, -40.087)-(-144.708, -9.525) reference; L17 (-139.454, -9.525)-(-118.712, -40.087) reference; L18 (-175.545, 40.087)-(-196.287, 9.525) reference; L19 (-201.541, 9.525)-(-222.283, 40.087) reference; L20 (-222.283, 43.653)-(-201.541, 74.216) reference; L21 (-196.287, 74.216)-(-175.545, 43.653) reference; L22 (-118.712, 40.087)-(-139.454, 9.525) reference; L23 (-144.708, 9.525)-(-165.45, 40.087) reference; L24 (-165.45, 43.653)-(-144.708, 74.216) reference; L25 (-139.454, 74.216)-(-118.712, 43.653) reference; L26 (-229.957, -32.345)-(-250.699, -1.783) reference; L27 (-250.699, 1.783)-(-229.957, 32.345) reference; L28 (-224.703, 32.345)-(-203.961, 1.783) reference; L29 (-203.961, -1.783)-(-224.703, -32.345) reference; L30 (-173.125, -32.345)-(-193.867, -1.783) reference; L31 (-193.867, 1.783)-(-173.125, 32.345) reference; L32 (-167.87, 32.345)-(-147.128, 1.783) reference; L33 (-147.128, -1.783)-(-167.87, -32.345) reference; L34 (-116.292, -32.345)-(-137.034, -1.783) reference; L35 (-137.034, 1.783)-(-116.292, 32.345) reference; L36 (-111.038, 32.345)-(-90.296, 1.783) reference; L37 (-90.296, -1.783)-(-111.038, -32.345) reference; L38 (-260.793, -1.783)-(-277.424, -26.288) reference; L39 (-280.325, -25.396)-(-280.325, 25.396) reference; L40 (-277.424, 26.288)-(-260.793, 1.783) reference; L41 (-95.25, -79.375)-(-304.8, -79.375); L42 (-304.8, -79.375)-(-304.8, 79.375); L43 (-304.8, 79.375)-(-95.25, 79.375); L44 (-95.25, 79.375)-(-95.25, -79.375); L45 (-95.25, -79.375)-(-304.8, 79.375); L46 (-304.8, -79.375)-(-95.25, 79.375); C1 r 2.489 at (-292.1, 82.55) reference; C2 r 2.489 at (-292.1, 69.85) reference; C3 r 2.489 at (-292.1, 57.15) reference; C4 r 2.489 at (-292.1, 44.45) reference; C5 r 2.489 at (-292.1, 31.75) reference; C6 r 2.489 at (-292.1, 19.05) reference; C7 r 2.489 at (-292.1, 6.35) reference; C8 r 2.489 at (-292.1, -82.55) reference; C9 r 2.489 at (-292.1, -69.85) reference; C10 r 2.489 at (-292.1, -57.15) reference; C11 r 2.489 at (-292.1, -44.45) reference; C12 r 2.489 at (-292.1, -31.75) reference; C13 r 2.489 at (-292.1, -19.05) reference; C14 r 2.489 at (-292.1, -6.35) reference; C15 r 2.489 at (-292.1, 0) reference; A1 r 3.175 centre (-255.746, -72.433) between (-258.373, -74.216) and (-253.119, -74.216) reference; A2 r 3.175 centre (-276.488, -41.87) between (-279.115, -40.087) and (-279.115, -43.653) reference; A3 r 3.175 centre (-255.746, -11.308) between (-253.119, -9.525) and (-258.373, -9.525) reference; A4 r 3.175 centre (-235.004, -41.87) between (-232.377, -43.653) and (-232.377, -40.087) reference; A5 r 3.175 centre (-255.746, 11.308) between (-258.373, 9.525) and (-253.119, 9.525) reference; A6 r 3.175 centre (-276.488, 41.87) between (-279.115, 43.653) and (-279.115, 40.087) reference; A7 r 3.175 centre (-255.746, 72.433) between (-253.119, 74.216) and (-258.373, 74.216) reference; A8 r 3.175 centre (-235.004, 41.87) between (-232.377, 40.087) and (-232.377, 43.653) reference; A9 r 3.175 centre (-198.914, -72.433) between (-201.541, -74.216) and (-196.287, -74.216) reference; A10 r 3.175 centre (-219.656, -41.87) between (-222.283, -40.087) and (-222.283, -43.653) reference; A11 r 3.175 centre (-198.914, -11.308) between (-196.287, -9.525) and (-201.541, -9.525) reference; A12 r 3.175 centre (-178.172, -41.87) between (-175.545, -43.653) and (-175.545, -40.087) reference; A13 r 3.175 centre (-142.081, -72.433) between (-144.708, -74.216) and (-139.454, -74.216) reference; A14 r 3.175 centre (-162.823, -41.87) between (-165.45, -40.087) and (-165.45, -43.653) reference; A15 r 3.175 centre (-142.081, -11.308) between (-139.454, -9.525) and (-144.708, -9.525) reference; A16 r 3.175 centre (-121.339, -41.87) between (-118.712, -43.653) and (-118.712, -40.087) reference; A17 r 3.175 centre (-198.914, 11.308) between (-201.541, 9.525) and (-196.287, 9.525) reference; A18 r 3.175 centre (-219.656, 41.87) between (-222.283, 43.653) and (-222.283, 40.087) reference; A19 r 3.175 centre (-198.914, 72.433) between (-196.287, 74.216) and (-201.541, 74.216) reference; A20 r 3.175 centre (-178.172, 41.87) between (-175.545, 40.087) and (-175.545, 43.653) reference; A21 r 3.175 centre (-142.081, 11.308) between (-144.708, 9.525) and (-139.454, 9.525) reference; A22 r 3.175 centre (-162.823, 41.87) between (-165.45, 43.653) and (-165.45, 40.087) reference; A23 r 3.175 centre (-142.081, 72.433) between (-139.454, 74.216) and (-144.708, 74.216) reference; A24 r 3.175 centre (-121.339, 41.87) between (-118.712, 40.087) and (-118.712, 43.653) reference; A25 r 3.175 centre (-248.072, 0) between (-250.699, 1.783) and (-250.699, -1.783) reference; A26 r 3.175 centre (-227.33, 30.563) between (-224.703, 32.345) and (-229.957, 32.345) reference; A27 r 3.175 centre (-206.588, 0) between (-203.961, -1.783) and (-203.961, 1.783) reference; A28 r 3.175 centre (-227.33, -30.563) between (-229.957, -32.345) and (-224.703, -32.345) reference; A29 r 3.175 centre (-191.239, 0) between (-193.867, 1.783) and (-193.867, -1.783) reference; A30 r 3.175 centre (-170.498, 30.563) between (-167.87, 32.345) and (-173.125, 32.345) reference; A31 r 3.175 centre (-149.756, 0) between (-147.128, -1.783) and (-147.128, 1.783) reference; A32 r 3.175 centre (-170.498, -30.563) between (-173.125, -32.345) and (-167.87, -32.345) reference; A33 r 3.175 centre (-134.407, 0) between (-137.034, 1.783) and (-137.034, -1.783) reference; A34 r 3.175 centre (-113.665, 30.563) between (-111.038, 32.345) and (-116.292, 32.345) reference; A35 r 3.175 centre (-92.923, 0) between (-90.296, -1.783) and (-90.296, 1.783) reference; A36 r 3.175 centre (-113.665, -30.563) between (-116.292, -32.345) and (-111.038, -32.345) reference; A37 r 1.587 centre (-278.738, -25.396) between (-280.325, -25.396) and (-277.424, -26.288) reference; A38 r 1.587 centre (-278.738, 25.396) between (-277.424, 26.288) and (-280.325, 25.396) reference; A39 r 3.175 centre (-263.421, 0) between (-260.793, -1.783) and (-260.793, 1.783) reference; 4 further points
  constraints: 12 end point, 4 midpoint, 2 parallel, 1 horizontal, 1 horizontal alignment, 1 perpendicular, 1 point on line
  dimensions: "d214" = 158.75 distance between parallel lines of L41 L43; "d215" = 209.55 distance between parallel lines of L1 L44
cut "Cut20" sketch "Sketch23" dims "d216" = 3.175 (derived), "d217" = 0
node "Face3"
  sketch "Sketch24"
    geometry: L1 (-304.8, 79.375)-(-304.8, 88.9) reference; L2 (242.08, -329.309)-(212.58, -329.309) reference; L3 (-304.8, -79.375)-(-95.25, -79.375); L4 (-95.25, 79.375)-(-304.8, 79.375); L5 (-304.8, -85.725)-(-88.9, -85.725); L6 (-88.9, 85.725)-(-304.8, 85.725); L7 (-304.8, 85.725)-(-304.8, 79.375); L8 (-304.8, -79.375)-(-304.8, -85.725); L9 (185.248, -329.309)-(155.747, -329.309) reference; L10 (-88.9, 85.725)-(-88.9, -85.725); L11 (-95.25, -79.375)-(-95.25, 79.375); 7 further points; 1 other entity
    constraints: 16 end point, 2 collinear, 2 horizontal, 2 parallel, 2 vertical alignment, 1 perpendicular, 2 other
    dimensions: "d218" = 6.35 distance between parallel lines of L6 L4; "d226" = 6.35 horizontal distance of L6.start L4.start; "d227" = 6.35 distance between parallel lines of L3 L5 (derived)
feature "Corner Round17" dims "d224" = 6.35
mirror "Mirror19"
feature "Corner Round18" dims "d225" = 6.35
sketch "Sketch25" dims "d534" = 4.9784
  geometry: L1 (-280.325, -326.134)-(-280.325, -309.566) reference; L2 (0, 0)-(20.742, 0); L3 (0, 0)-(0, 30.563); C1 r 2.489 at (292.1, -95.25) reference; C2 r 2.489 at (-292.1, -82.55); C3 r 2.489 at (-292.1, 82.55); C4 r 2.489 at (292.1, 82.55); A1 r 3.175 centre (0, 30.563) between (2.627, 32.345) and (-2.627, 32.345) reference; A2 r 3.175 centre (20.742, 0) between (23.369, -1.783) and (23.369, 1.783) reference; 3 further points
  constraints: 4 end point, 3 centre point, 3 symmetric about line, 2 perpendicular, 1 vertical alignment, 5 other
  dimensions: "d533" = 12.7 distance of C1.centre point (292.1, -82.55)
hole "Hole1" sketch "Sketch25" diameter "d228" = 4.9784; stored, may be unused: countersink angle "d232" = 82 deg, drill point angle "d234" = 118 deg; dims "d229" = 19.05, "d230" = 9.525, "d231" = 6.35, "d233" = 3.175 (derived)
node "Face4"
  sketch "Sketch26" dims "d243" = 25.4
    geometry: L1 (260.93, -85.725)-(280.325, -85.725) reference; L2 (-101.6, -79.375)-(-298.45, -79.375) reference; L3 (-280.325, -109.137)-(-280.325, -85.725) reference; L4 (-280.325, 85.725)-(-260.93, 85.725) reference; L5 (-304.8, -85.725)-(-304.8, -69.85); L6 (-298.45, -63.5)-(-286.675, -63.5); L7 (-280.325, -69.85)-(-280.325, -79.375); C1 r 2.489 at (-292.1, -82.55); C2 r 2.489 at (-292.1, -82.55); C3 r 2.489 at (-292.1, -69.85); C4 r 2.489 at (-292.1, -95.25) reference; A1 r 6.35 centre (-298.45, -85.725) between (-298.45, -79.375) and (-304.8, -85.725) reference; A2 r 6.35 centre (-298.45, -69.85) between (-298.45, -63.5) and (-304.8, -69.85); A3 r 6.35 centre (-286.675, -69.85) between (-280.325, -69.85) and (-286.675, -63.5); 1 further point
    constraints: 6 end point, 5 centre point, 5 tangent, 4 point on circle, 2 parallel, 2 vertical alignment, 1 coincident, 1 equal radius, 1 perpendicular, 1 point on line, 1 vertical, 2 other
    dimensions: "d236" = 6.35 radius of A2; "d237" = 19.05 distance from line of L6 C1.centre; "d240" = 12.7 distance of C2.centre C3.centre; "d535" = 12.7 distance of C4.centre C1.centre; "d536" = 4.9784 diameter of C1; "d537" = 4.9784 diameter of C3
mirror "Mirror20"
mirror "Mirror21"
sketch "Sketch27"
  geometry: L1 (-192.087, 330.2)-(-214.312, 330.2) reference; L2 (-222.987, 342.163)-(-226.355, 345.53) reference; L3 (-298.45, 349.25)-(-235.335, 349.25) reference; L4 (-304.8, 127)-(-304.8, 342.9) reference; L5 (222.987, -342.163)-(226.355, -345.53) reference; L6 (-298.45, 342.9)-(-292.1, 336.55); L7 (-298.45, 349.25)-(-235.335, 349.25); L8 (-226.355, 345.53)-(-222.987, 342.163); L9 (-214.312, 330.2)-(-192.087, 330.2); L10 (-177.8, 344.487)-(-177.8, 349.25); L11 (-235.335, 349.25)-(-177.8, 349.25); L12 (-301.08, 270.805)-(-297.713, 267.437); L13 (-285.75, 258.763)-(-285.75, 236.538); L14 (-300.037, 222.25)-(-304.8, 222.25); L15 (-304.8, 279.785)-(-304.8, 222.25); L16 (-304.8, 342.9)-(-304.8, 279.785); L17 (-285.75, 185.738)-(-285.75, 207.963); L18 (-292.1, 179.388)-(-298.45, 179.387); L19 (-304.8, 173.037)-(-304.8, 222.25); C1 r 2.489 at (-292.1, 336.55) reference; A1 r 6.35 centre (-141.287, 336.55) between (-141.287, 330.2) and (-134.938, 336.55) reference; A2 r 6.35 centre (-163.512, 336.55) between (-169.862, 336.55) and (-163.512, 330.2) reference; A3 r 7.937 centre (-177.8, 336.55) between (-169.862, 336.55) and (-185.737, 336.55) reference; A4 r 6.35 centre (-192.087, 336.55) between (-192.087, 330.2) and (-185.737, 336.55) reference; A5 r 6.35 centre (-214.312, 336.55) between (-220.662, 336.55) and (-214.312, 330.2) reference; A6 r 7.937 centre (-228.6, 336.55) between (-220.662, 336.55) and (-222.987, 342.163) reference; A7 r 12.7 centre (-235.335, 336.55) between (-226.355, 345.53) and (-235.335, 349.25) reference; A8 r 6.35 centre (-298.45, 342.9) between (-298.45, 349.25) and (-304.8, 342.9) reference; A9 r 12.7 centre (-235.335, 336.55) between (-226.355, 345.53) and (-235.335, 349.25); A10 r 7.938 centre (-228.6, 336.55) between (-220.662, 336.55) and (-222.987, 342.163); A11 r 6.35 centre (-214.312, 336.55) between (-220.662, 336.55) and (-214.312, 330.2); A12 r 6.35 centre (-192.087, 336.55) between (-192.087, 330.2) and (-185.737, 336.55); A13 r 7.938 centre (-177.8, 336.55) between (-177.8, 344.487) and (-185.737, 336.55); A14 r 12.7 centre (-292.1, 279.785) between (-304.8, 279.785) and (-301.08, 270.805); A15 r 7.937 centre (-292.1, 273.05) between (-297.713, 267.437) and (-292.1, 265.113); A16 r 6.35 centre (-292.1, 258.763) between (-285.75, 258.763) and (-292.1, 265.113); A17 r 6.35 centre (-292.1, 236.538) between (-292.1, 230.188) and (-285.75, 236.538); A18 r 7.937 centre (-292.1, 222.25) between (-292.1, 230.188) and (-292.1, 214.313); A19 r 7.937 centre (-292.1, 222.25) between (-292.1, 230.188) and (-292.1, 214.313); A20 r 6.35 centre (-292.1, 207.963) between (-285.75, 207.963) and (-292.1, 214.313); A21 r 6.35 centre (-292.1, 185.738) between (-292.1, 179.388) and (-285.75, 185.738); A22 r 6.35 centre (-298.45, 173.038) between (-298.45, 179.387) and (-304.8, 173.037); 1 further point
  constraints: 30 point on circle, 28 end point, 21 symmetric about line, 20 tangent, 14 centre point, 4 perpendicular, 1 collinear, 1 horizontal alignment, 1 parallel, 1 point on line, 8 other
  dimensions: "d250" = 6.35 radius of A22
cut "Cut21" sketch "Sketch27" dims "d251" = 3.175 (derived), "d252" = 0
mirror "Mirror22"
mirror "Mirror23"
